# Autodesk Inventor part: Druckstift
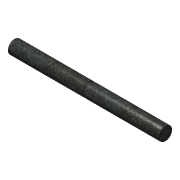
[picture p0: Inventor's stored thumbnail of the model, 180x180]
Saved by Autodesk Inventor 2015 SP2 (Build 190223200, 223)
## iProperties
Created: 2017-07
Material: St
Document SubType Name: Modeling
Designer: krebs
Density: 7.85 g/cm^3
Appearance: Platte
Part Number: Druckstift
Mass: 27.0691 g
Surface Area: 20.7188 cm^2
Volume: 3.44829 cm^3
Author: krebs
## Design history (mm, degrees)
sketch "Skizze1"
  geometry: L1 (-45, -0.005)-(-45, 3.995); L2 (-45, 3.995)-(-0.75, 3.995); L3 (-0.75, 3.995)-(-0.75, 3.495); L4 (-0.75, 3.495)-(0.75, 3.495); L5 (0.75, 3.495)-(0.75, 3.995); L6 (0.75, 3.995)-(45, 3.995); L7 (45, 3.995)-(45, -0.005); L8 (-45, -0.005)-(45, -0.005); L9 (0, 3.495)-(0, -0.005); L10 (0, -0.805)-(0, 4.795) reference; 1 further point
  constraints: 18 end point, 5 perpendicular, 2 collinear, 2 midpoint, 2 vertical, 1 horizontal, 1 other
  dimensions: "d4" = 1.5 distance of L3.end L4.end; "d11" = 90 distance between parallel lines of L7 L1; "d12" = 8 diameter of L6 L8; "d17" = 0.5 distance between parallel lines of L2 L4
revolve "Grundkörper" sketch "Skizze1" stored, may be unused: angle "d10" = 90 deg
chamfer "Fase2" distance "d13" = 0.2; stored, may be unused: second distance "d14" = 2, angle "d15" = 45 deg
node "Mittelebene yz"
node "Volumenkörper1"
